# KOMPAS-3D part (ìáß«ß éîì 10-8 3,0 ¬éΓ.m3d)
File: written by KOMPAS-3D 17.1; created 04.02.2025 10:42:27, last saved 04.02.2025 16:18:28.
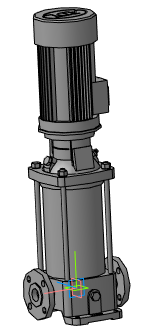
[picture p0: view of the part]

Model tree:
1. Операция без истории:1  (labels: Насос ВМН 10-8 3,0 кВт)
